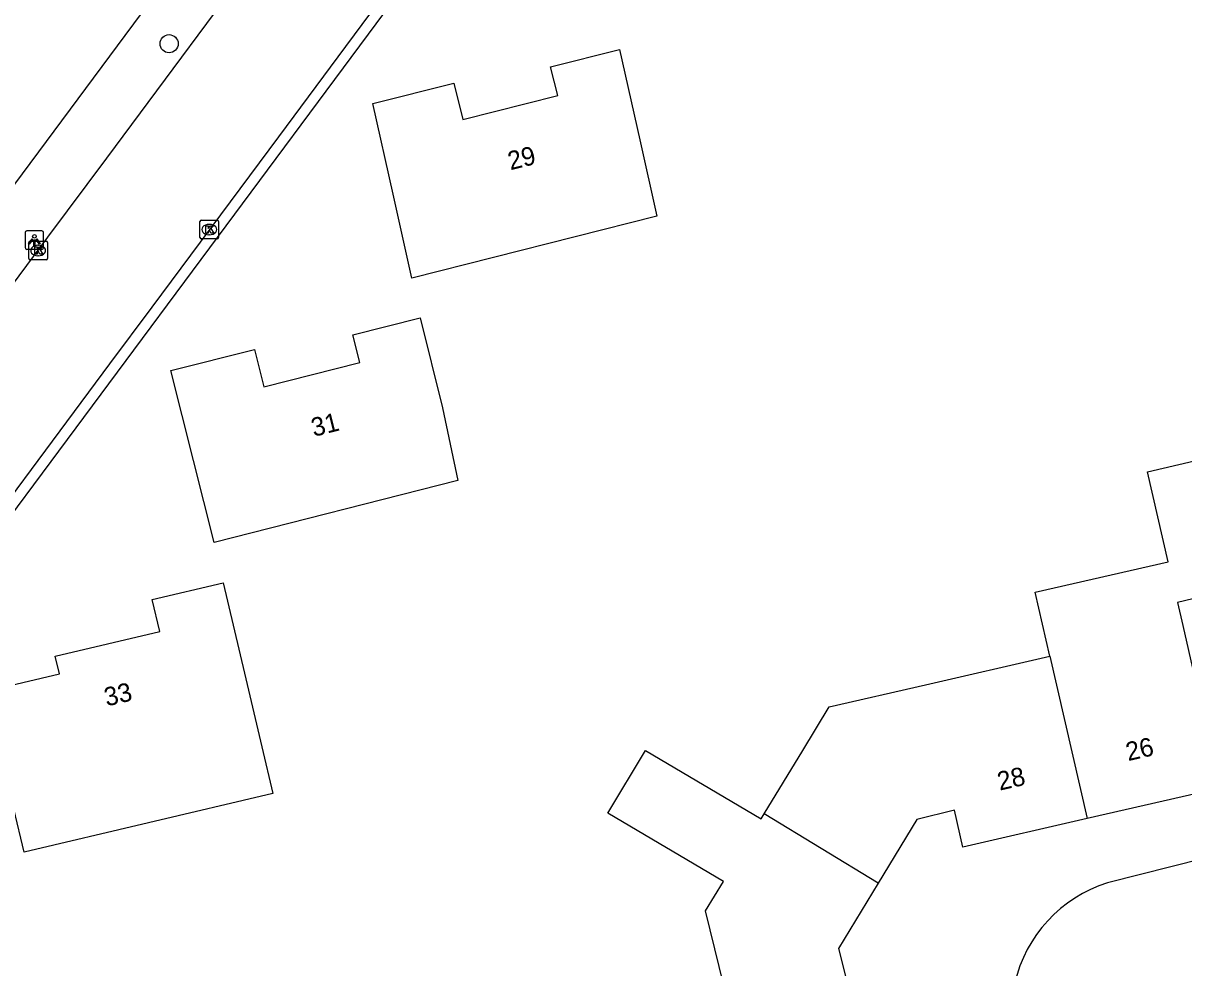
# Model space of a CAD drawing. Extents: x 157663 to 158496, y 379212 to 380934.
# Drawn here: x 158093.6 to 158156.2, y 380530.4 to 380581.3 of the extents above; entities that cross this region are included whole.
import ezdxf

# ---------------------------------------------------------------- set-up
doc = ezdxf.new("R2010")
doc.units = 0
for name, color, linetype in [('IMGEO_Boom', 7, 'Continuous'), ('IMGEO_Kolk', 7, 'Continuous'), ('IMGEO_Lichtpunt', 7, 'Continuous'), ('IMGEO_Pand', 7, 'Continuous'), ('IMGEO_Pand_nummerreeks', 7, 'Continuous'), ('IMGEO_Rijbaan_lokaal_open', 7, 'Continuous'), ('IMGEO_Voetpad_open', 7, 'Continuous')]:
    doc.layers.add(name, color=color, linetype=linetype)

msp = doc.modelspace()

# ---------------------------------------------------------------- linework, layer by layer
at = {"layer": 'IMGEO_Boom'}
msp.add_circle((158101.479, 380580.171), 0.489, dxfattribs=at)
at = {"layer": 'IMGEO_Kolk'}
for p, q in [((158103.14, 380569.733), (158103.14, 380570.585)), ((158103.215, 380570.659), (158104.067, 380570.659)), ((158103.628, 380570.439), (158103.653, 380570.439)), ((158104.141, 380570.585), (158104.141, 380569.733)), ((158093.994, 380569.528), (158094.846, 380569.528)), ((158104.067, 380569.659), (158103.215, 380569.659)), ((158103.651, 380569.879), (158103.626, 380569.879)), ((158093.919, 380568.602), (158093.919, 380569.454)), ((158094.407, 380569.308), (158094.432, 380569.308)), ((158094.92, 380569.454), (158094.92, 380568.602)), ((158094.846, 380568.528), (158093.994, 380568.528)), ((158094.43, 380568.748), (158094.405, 380568.748))]:
    msp.add_line(p, q, dxfattribs=at)
for points in [[(158103.14, 380569.733), (158103.14, 380570.585)], [(158103.215, 380570.659), (158104.067, 380570.659)], [(158103.461, 380570.359), (158103.584, 380570.359), (158103.584, 380570.208), (158103.714, 380570.359), (158103.878, 380570.359), (158103.732, 380570.208), (158103.885, 380569.959), (158103.733, 380569.959), (158103.648, 380570.123), (158103.584, 380570.056), (158103.584, 380569.959), (158103.461, 380569.959), (158103.461, 380570.359)], [(158104.141, 380570.585), (158104.141, 380569.733)], [(158093.994, 380569.528), (158094.846, 380569.528)], [(158104.067, 380569.659), (158103.215, 380569.659)], [(158093.919, 380568.602), (158093.919, 380569.454)], [(158094.24, 380569.228), (158094.363, 380569.228), (158094.363, 380569.077), (158094.493, 380569.228), (158094.657, 380569.228), (158094.511, 380569.077), (158094.664, 380568.828), (158094.512, 380568.828), (158094.427, 380568.992), (158094.363, 380568.925), (158094.363, 380568.828), (158094.24, 380568.828), (158094.24, 380569.228)], [(158094.92, 380569.454), (158094.92, 380568.602)], [(158094.846, 380568.528), (158093.994, 380568.528)]]:
    msp.add_lwpolyline(points, dxfattribs=at)
for centre, start, end in [((158103.217, 380570.583), 91.55205, 178.44795), ((158103.217, 380570.583), 91.55205, 178.44795), ((158104.065, 380570.583), 1.55205, 88.44795), ((158104.065, 380570.583), 1.55205, 88.44795), ((158093.996, 380569.452), 91.55205, 178.44795), ((158093.996, 380569.452), 91.55205, 178.44795), ((158094.844, 380569.452), 1.55205, 88.44795), ((158094.844, 380569.452), 1.55205, 88.44795), ((158103.217, 380569.735), 181.55205, 268.44795), ((158103.217, 380569.735), 181.55205, 268.44795), ((158104.065, 380569.735), 271.55205, 358.44795), ((158104.065, 380569.735), 271.55205, 358.44795), ((158093.996, 380568.604), 181.55205, 268.44795), ((158093.996, 380568.604), 181.55205, 268.44795), ((158094.844, 380568.604), 271.55205, 358.44795), ((158094.844, 380568.604), 271.55205, 358.44795)]:
    msp.add_arc(centre, 0.0765, start, end, dxfattribs=at)
for centre, major_axis, ratio, start_param, end_param in [((158103.627, 380570.159), (-0.387, 0.002), 0.722429, 4.712389, 7.853982), ((158103.652, 380570.159), (-0.39, 0.002), 0.717154, 1.570796, 4.712389), ((158094.406, 380569.028), (-0.387, 0.002), 0.722429, 4.712389, 7.853982), ((158094.431, 380569.028), (-0.39, 0.002), 0.717154, 1.570796, 4.712389)]:
    msp.add_ellipse(centre, major_axis=major_axis, ratio=ratio, start_param=start_param, end_param=end_param, dxfattribs=at)
at = {"layer": 'IMGEO_Lichtpunt'}
for p, q in [((158093.717, 380569.993), (158093.717, 380569.186)), ((158093.717, 380569.993), (158093.717, 380569.186)), ((158094.619, 380570.088), (158093.811, 380570.088)), ((158094.619, 380570.088), (158093.811, 380570.088)), ((158094.713, 380569.186), (158094.713, 380569.993)), ((158094.713, 380569.186), (158094.713, 380569.993)), ((158093.811, 380569.092), (158094.619, 380569.092)), ((158093.811, 380569.092), (158094.619, 380569.092))]:
    msp.add_line(p, q, dxfattribs=at)
for points in [[(158094.091, 380569.657), (158094.13, 380569.629), (158093.942, 380569.367), (158093.904, 380569.394), (158094.091, 380569.657)], [(158094.193, 380569.609), (158094.24, 380569.609), (158094.24, 380569.287), (158094.193, 380569.287), (158094.193, 380569.609)], [(158094.303, 380569.629), (158094.341, 380569.656), (158094.528, 380569.394), (158094.489, 380569.366), (158094.303, 380569.629)]]:
    msp.add_lwpolyline(points, dxfattribs=at)
msp.add_circle((158094.216, 380569.791), 0.0994, dxfattribs=at)
for centre, start, end in [((158093.811, 380569.993), 90, 180), ((158093.811, 380569.993), 90, 180), ((158094.619, 380569.993), 0, 90), ((158094.619, 380569.993), 0, 90), ((158093.811, 380569.186), 180, 270), ((158093.811, 380569.186), 180, 270), ((158094.619, 380569.186), 270, 0), ((158094.619, 380569.186), 270, 360)]:
    msp.add_arc(centre, 0.0946, start, end, dxfattribs=at)
at = {"layer": 'IMGEO_Pand'}
for points in [[(158127.767, 380570.872), (158114.566, 380567.532), (158113.55, 380572.072), (158112.458, 380576.951), (158116.821, 380578.047), (158117.314, 380576.087), (158122.433, 380577.374), (158122.041, 380578.932), (158125.752, 380579.865), (158126.845, 380574.986), (158127.767, 380570.872)], [(158116.221, 380560.553), (158117.043, 380556.643), (158103.898, 380553.295), (158102.787, 380557.716), (158101.568, 380562.565), (158106.074, 380563.697), (158106.579, 380561.687), (158111.755, 380562.988), (158111.377, 380564.491), (158115.002, 380565.402), (158116.221, 380560.553)], [(158148.947, 380547.167), (158148.157, 380550.608), (158155.319, 380552.251), (158154.202, 380557.11), (158155.893, 380557.499), (158157.584, 380557.887), (158157.76, 380557.928)], [(158105.541, 380546.256), (158106.483, 380542.274), (158107.075, 380539.774), (158093.659, 380536.6), (158093.105, 380538.943), (158091.604, 380545.287), (158095.565, 380546.224), (158095.342, 380547.17), (158100.978, 380548.503), (158100.573, 380550.218), (158104.39, 380551.121), (158105.541, 380546.256)], [(158159.381, 380550.88), (158159.224, 380550.844), (158156.65, 380550.252), (158155.822, 380550.062), (158156.109, 380548.813), (158157.253, 380543.835), (158158.12, 380540.062), (158150.955, 380538.416)], [(158133.557, 380538.672), (158135.628, 380542.09), (158137.048, 380544.433), (158142.253, 380545.629), (158148.947, 380547.167)], [(158148.947, 380547.167), (158150.955, 380538.416)], [(158133.606, 380520.353), (158130.392, 380533.449), (158131.349, 380535.028), (158125.116, 380538.715), (158127.16, 380542.088), (158133.393, 380538.401), (158133.557, 380538.672)], [(158150.955, 380538.416), (158144.264, 380536.878), (158143.806, 380538.867), (158141.772, 380538.367), (158139.697, 380534.943)], [(158139.697, 380534.943), (158133.557, 380538.672)], [(158139.697, 380534.943), (158137.561, 380531.418), (158138.176, 380528.914), (158140.73, 380529.541), (158142.469, 380522.455)]]:
    msp.add_lwpolyline(points, dxfattribs=at)
at = {"layer": 'IMGEO_Rijbaan_lokaal_open'}
for points in [[(158085.035, 380556.423), (158094.943, 380569.745), (158098.128, 380574.013), (158107.086, 380586.099), (158111.202, 380591.638), (158119.072, 380602.259), (158123.165, 380607.755), (158135.53, 380624.378)], [(158140.435, 380619.693), (158132.676, 380609.174), (158129.96, 380605.535), (158121.722, 380594.507), (158119.02, 380590.852), (158110.981, 380580.03), (158107.373, 380575.162), (158100.542, 380565.978), (158098.266, 380562.93), (158089.025, 380550.498)]]:
    msp.add_lwpolyline(points, dxfattribs=at)
at = {"layer": 'IMGEO_Voetpad_open'}
for points in [[(158131.522, 380624.317), (158084.588, 380561.116)], [(158090.13, 380550.967), (158140.58, 380618.873)], [(158158.961, 380536.699), (158152.052, 380534.953)]]:
    msp.add_lwpolyline(points, dxfattribs=at)
msp.add_arc((158154.303, 380527.856), 7.446, 107.6009, 166.91967, dxfattribs=at)

# ---------------------------------------------------------------- texts
at = {"layer": 'IMGEO_Pand_nummerreeks'}
for s, rotation, p in [('29', 14.11259, (158119.872, 380573.348)), ('31', 14.10915, (158109.275, 380558.983)), ('33', 13.30408, (158098.11, 380544.455)), ('26', 12.94312, (158153.168, 380541.509)), ('28', 12.94145, (158146.243, 380539.918))]:
    msp.add_text(s, height=1, rotation=rotation, dxfattribs=at).set_placement(p)

doc.saveas('drawing.dxf')
